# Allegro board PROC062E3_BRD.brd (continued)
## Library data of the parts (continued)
C58-C61 = CAP: signal model: CAP_CAP0402_0-75_0.01UF_0.01uF
D1 = DIODE
D2 = DIODE_TVS_DUAL
D3 D5 D6 D8 D9 D15 D17 = DIODE_SCHOTTKY
D4 D16 = DIODE_ZENER_SOT23_13
D7 D10-D13 = DIODE_PESD
D14 = DIODE_ZENER
F1 = FUSE
FL1 FL3-FL7 FL9-FL36 FL38 = EMIFILTER_IND
FL2 = EMI_FILTER
FL8 = EMIFILTER_ACM
FL37 R1-R84 R87-R100 R103-R110 R112 R113 R115-R117 R119 R120 R122-R151 R153 R155 R156 R158-R161 R163-R167 R171-R179 R182 R184-R202 R210 R212-R225 R227-R233 R235-R240 R242-R252 R254-R297 R299-R341 R343-R347 R350-R354 R356-R359 R362-R409 R411-R429 R431 R440-R442 R447 R449-R458 R460 R462 R464 R467-R479 R481-R484 R486 R490 R495-R499 R501 R503-R516 R518 R520-R522 R524 R526-R528 R534-R536 R538-R540 R542-R593 R596 R600-R622 R624-R673 R675-R698 R700-R704 R707-R723 R728-R732 R735-R743 R745 = RESISTOR
J1 = CON_PWRJACK3_RAPC722
J2 = CON_POWERJACK_PD-40S
J3 = CON_USB_MINI-AB_10
J4 = HEADER_3X2
J5 = CON_BTOB_30X2_171446
J6 = HEADER_5X2
J8 J9 J33 J37 J43-J45 = HEADER_3X1
J10 = HEADER_10X2
J11 J30 = HEADER_6X1
J12 = CON_RJ45-14_LPJG16314A4NL
J13 J34 = CON_10X2
J14 = CON_RJ45-28_LPJG17512AONL
J15 J24-J29 J31 = HEADER_2X1
J16 J32 J36 = CON_PMC_30X2_F
J17 = CON_SDCARD9_1939870-1
J18 J35 = CON_PMC_60X2_HQCD
J19 = HEADER_7X1
J20 J21 = HEADER_5X1
J22 = CON_PMC_20X2_F
J23 J42 = CON_MUSB-B_5_1051640001
J38 = CON_FLEX_40X1_SH4
J39 = CON_FLEX_36X1_52559-3652
J40 = CON_5X2
J41 = CON_FLEX_40X1_FH12A-40S-0.5SH
L1-L11 = INDUCTOR
LD1-LD6 LD8-LD17 = LED_598-8170-107F
LD7 LD19 LD20 = DIODE_LED
LD18 = LED3_SML-LX15IGC
Q1 Q2 = MOSFET_IRFZ24NS
Q3-Q6 Q9-Q17 = MOSFET_BSS138LT1G
Q7 = MOSFET_IRLML6401TR
Q8 = MOSFET_BSS138
R101 R102 R111 R114 R118 R121 R152 R154 R157 R162 R168 R180 R181 R183 R209 R211 R438 R439 R463 R466 R494 R500 R517 R519 R523 R525 R537 R541 = RESISTOR: signal model: RES
R169 R170 R203-R208 R241 R253 R410 R430 R432 R448 R489 R491 R532 R533 R623 R674 R699 = RESISTOR: signal model: RESISTOR_RES0402_22E_22E
R234 R342 R348 R349 R355 R360 R361 R459 = RESISTOR-4TERM
R594 R595 R597-R599 = RESISTOR: signal model: RESISTOR_RES0201_100E_100E
R705 R706 = RESISTOR: signal model: RESISTOR_RES0402_0-5_10E_10E
R724-R727 = RESISTOR: signal model: RESISTOR_RES0402_22E_1%_22E_1%
RA1 RA3 RA5 RA9-RA11 = RESARR_ISO8_0402: signal model: RESA
RA2 RA4 RA7 = RESARR_ISO4: signal model: RESA1
RA6 RA12 RA13 RA15-RA17 = RESARR_ISO4
RA8 RA14 = RESARR_ISO8: signal model: RESARR_ISO8_RESA_0402-8_22E_22E
SW1 = SW3_B12JV
SW2 SW3 = SW10_218-10LPST
SW4 = SW4_CHS-02TA
SW5-SW8 = SW4_SKHUPLE010
TP1-TP32 TP34-TP62 TP64-TP76 TP79-TP88 = TESTPOINT
U1 = TLV71318PDQNR_X2SON4
U2 U3 U27 U67-U70 U93 = INA226AIDGS_MSOP10
U4 = TPD4S012DRY_SON6
U5 U76 = TPS73501DRVR_SON6
U6 U12 U19 U21 U85 = SN74AVC4T245RSV_UQFN16
U7 U46 = TCA9554APWR_TSSOP16
U8 U23 U65 U83 = SN74LVC2G157DCUR_VSSOP8
U9 = 24LC512-ESN_SOIC8
U10 = TPS51206DSQR_WSON10
U11 U115 = TPS2051BD_SOIC8
U13 U18 = MOSFET_SI4442DY
U14 = LM25118MH_HTSSOP20
U15 U58 = TPD4E004_SON6
U16 U20 U25 U33 U38 = MT40A1G8WE-083_FBGA78
U17 U39 U41 U90 U92 = SN74LVC1G32DBVR_SOT23-5
U22 U31 U88 = DP83867IRRGZ_VQFN48
U24 = MT25QL02GCBB8E12_TPBGA24
U26 = TS3L110PWG4_TSSOP16
U28 U48 U53 U55 U74 U82 U86 U104 U108 U113 = SN74LVC1G08DBVRE4_SOT23-5
U29 U109 = SN74AVC2T245RSWR_QFN10
U30 U37 U45 U87 U96 U103 = TXS0102DCUR_VSSOP8
U32 = CDCLVC1310RHBR_VQFN32
U34 = AM654X_BGA784
U35 = TPS3711DDCR_SOT23-6
U36 = SN74LVC1G04DCKR_SC70-5
U40 U63 = TPS62097RWKT_VQFNHR11
U42 = SN74CB3Q3257PWR_TSSOP16
U43 U95 U98 = SN74AVC4T245RGYR_QFN16
U44 U89 = TMP100NA/3K_SOT23-6
U47 = TPD6E001RSE_UQFN10
U49 = TPS3897ADRYR_SON6
U50 = SN74LVC1G11DCKR_SC70-6
U51 = MTFC16GAKAEJP_VFBGA153
U52 U54 = SN74LVC3G17DCUR_VSSOP8
U56 = AT24HC04B-TH-B_TSSOP8
U57 = TPS79601DRBR_SON8
U59 = TPS6236X_DSBGA16
U60 = LP5912-1-8DRVT_WSON6
U61 = TPS62480RNCT_VQFNHR16
U62 = MIC5060YML_MLF8
U64 = TPS62095RGTR_VQFN16
U66 = LM5060_MSOP10
U71 U72 U78 U81 = MOSFET_CSD18501Q5A
U73 = FT4232H _LQFP64
U75 = LM5140QRWGTQ1_VQFNP40
U77 = MT35XU512ABA1G12_TPBGA24
U79 = 93LC46B_MSOP8
U80 = TPS54334DRCT_VSON10
U84 = TPIC2810D_SOIC16
U91 = MCP79410_SOIC8
U94 = TPS62085RLTR_VSONHR7
U97 U101 = SN74AVC2T244DQMR_X2SON8
U99 = TCA6424ARGJR_QFN32
U100 = TXB0108RGYR_VQFN20
U102 U105 = SN74AVC8T245RHL_QFN24
U106 = TM4C1294NCPDTT3R_TQFP128
U107 = LM4040B25IDCKR_SC70-5
U110 = TCA9555RTWR_WQFN24
U111 = TXS0108ERGYR_QFN20
U112 U114 = OSC_KC2520B
Y1-Y3 Y5 = CRY
Y4 Y6 = CRY4_13

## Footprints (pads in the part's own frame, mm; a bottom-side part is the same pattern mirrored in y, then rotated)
BATTH2_796136_1080X750_SMD_6-9
  rect 3.15x4.775 smd: 1(-15.52,0) 2(15.52,0)
BGA784_31-49_910X910_1-7
  round 0.457 smd: A1(-10.8,10.8) A2(-10,10.8) A3(-9.2,10.8) A4(-8.4,10.8) A5(-7.6,10.8) A6(-6.8,10.8) A7(-6,10.8) A8(-5.2,10.8) A9(-4.4,10.8) A10(-3.6,10.8) A11(-2.8,10.8) A12(-2,10.8) A13(-1.2,10.8) A14(-0.4,10.8) A15(0.4,10.8) A16(1.2,10.8) A17(2,10.8) A18(2.8,10.8) A19(3.6,10.8) A20(4.4,10.8) A21(5.2,10.8) A22(6,10.8) A23(6.8,10.8) A24(7.6,10.8) A25(8.4,10.8) A26(9.2,10.8) A27(10,10.8) A28(10.8,10.8) AA1(-10.8,-5.2) AA2(-10,-5.2) AA3(-9.2,-5.2) AA4(-8.4,-5.2) AA5(-7.6,-5.2) AA6(-6.8,-5.2) AA7(-6,-5.2) AA8(-5.2,-5.2) AA9(-4.4,-5.2) AA10(-3.6,-5.2) AA11(-2.8,-5.2) AA12(-2,-5.2) AA13(-1.2,-5.2) AA14(-0.4,-5.2) AA15(0.4,-5.2) AA16(1.2,-5.2) AA17(2,-5.2) AA18(2.8,-5.2) AA19(3.6,-5.2) AA20(4.4,-5.2) AA21(5.2,-5.2) AA22(6,-5.2) AA23(6.8,-5.2) AA24(7.6,-5.2) AA25(8.4,-5.2) AA26(9.2,-5.2) AA27(10,-5.2) AA28(10.8,-5.2) AB1(-10.8,-6) AB2(-10,-6) AB3(-9.2,-6) AB4(-8.4,-6) AB5(-7.6,-6) AB6(-6.8,-6) AB7(-6,-6) AB8(-5.2,-6) AB9(-4.4,-6) AB10(-3.6,-6) AB11(-2.8,-6) AB12(-2,-6) AB13(-1.2,-6) AB14(-0.4,-6) AB15(0.4,-6) AB16(1.2,-6) AB17(2,-6) AB18(2.8,-6) AB19(3.6,-6) AB20(4.4,-6) AB21(5.2,-6) AB22(6,-6) AB23(6.8,-6) AB24(7.6,-6) AB25(8.4,-6) AB26(9.2,-6) AB27(10,-6) AB28(10.8,-6) AC1(-10.8,-6.8) AC2(-10,-6.8) AC3(-9.2,-6.8) AC4(-8.4,-6.8) AC5(-7.6,-6.8) AC6(-6.8,-6.8) AC7(-6,-6.8) AC8(-5.2,-6.8) AC9(-4.4,-6.8) AC10(-3.6,-6.8) AC11(-2.8,-6.8) AC12(-2,-6.8) AC13(-1.2,-6.8) AC14(-0.4,-6.8) AC15(0.4,-6.8) AC16(1.2,-6.8) AC17(2,-6.8) AC18(2.8,-6.8) AC19(3.6,-6.8) AC20(4.4,-6.8) AC21(5.2,-6.8) AC22(6,-6.8) AC23(6.8,-6.8) AC24(7.6,-6.8) AC25(8.4,-6.8) AC26(9.2,-6.8) AC27(10,-6.8) AC28(10.8,-6.8) AD1(-10.8,-7.6) AD2(-10,-7.6) AD3(-9.2,-7.6) AD4(-8.4,-7.6) AD5(-7.6,-7.6) AD6(-6.8,-7.6) AD7(-6,-7.6) AD8(-5.2,-7.6) AD9(-4.4,-7.6) AD10(-3.6,-7.6) AD11(-2.8,-7.6) AD12(-2,-7.6) AD13(-1.2,-7.6) AD14(-0.4,-7.6) AD15(0.4,-7.6) AD16(1.2,-7.6) AD17(2,-7.6) AD18(2.8,-7.6) AD19(3.6,-7.6) AD20(4.4,-7.6) AD21(5.2,-7.6) AD22(6,-7.6) AD23(6.8,-7.6) AD24(7.6,-7.6) AD25(8.4,-7.6) AD26(9.2,-7.6) AD27(10,-7.6) AD28(10.8,-7.6) AE1(-10.8,-8.4) AE2(-10,-8.4) AE3(-9.2,-8.4) AE4(-8.4,-8.4) AE5(-7.6,-8.4) AE6(-6.8,-8.4) AE7(-6,-8.4) AE8(-5.2,-8.4) AE9(-4.4,-8.4) AE10(-3.6,-8.4) AE11(-2.8,-8.4) AE12(-2,-8.4) AE13(-1.2,-8.4) AE14(-0.4,-8.4) AE15(0.4,-8.4) AE16(1.2,-8.4) AE17(2,-8.4) AE18(2.8,-8.4) AE19(3.6,-8.4) AE20(4.4,-8.4) AE21(5.2,-8.4) AE22(6,-8.4) AE23(6.8,-8.4) AE24(7.6,-8.4) AE25(8.4,-8.4) AE26(9.2,-8.4) AE27(10,-8.4) AE28(10.8,-8.4) AF1(-10.8,-9.2) AF2(-10,-9.2) AF3(-9.2,-9.2) AF4(-8.4,-9.2) AF5(-7.6,-9.2) AF6(-6.8,-9.2) AF7(-6,-9.2) AF8(-5.2,-9.2) AF9(-4.4,-9.2) AF10(-3.6,-9.2) AF11(-2.8,-9.2) AF12(-2,-9.2) AF13(-1.2,-9.2) AF14(-0.4,-9.2) AF15(0.4,-9.2) AF16(1.2,-9.2) AF17(2,-9.2) AF18(2.8,-9.2) AF19(3.6,-9.2) AF20(4.4,-9.2) AF21(5.2,-9.2) AF22(6,-9.2) AF23(6.8,-9.2) AF24(7.6,-9.2) AF25(8.4,-9.2) AF26(9.2,-9.2) AF27(10,-9.2) AF28(10.8,-9.2) AG1(-10.8,-10) AG2(-10,-10) AG3(-9.2,-10) AG4(-8.4,-10) AG5(-7.6,-10) AG6(-6.8,-10) AG7(-6,-10) AG8(-5.2,-10) AG9(-4.4,-10) AG10(-3.6,-10) AG11(-2.8,-10) AG12(-2,-10) AG13(-1.2,-10) AG14(-0.4,-10) AG15(0.4,-10) AG16(1.2,-10) AG17(2,-10) AG18(2.8,-10) AG19(3.6,-10) AG20(4.4,-10) AG21(5.2,-10) AG22(6,-10) AG23(6.8,-10) AG24(7.6,-10) AG25(8.4,-10) AG26(9.2,-10) AG27(10,-10) AG28(10.8,-10) AH1(-10.8,-10.8) AH2(-10,-10.8) AH3(-9.2,-10.8) AH4(-8.4,-10.8) AH5(-7.6,-10.8) AH6(-6.8,-10.8) AH7(-6,-10.8) AH8(-5.2,-10.8) AH9(-4.4,-10.8) AH10(-3.6,-10.8) AH11(-2.8,-10.8) AH12(-2,-10.8) AH13(-1.2,-10.8) AH14(-0.4,-10.8) AH15(0.4,-10.8) AH16(1.2,-10.8) AH17(2,-10.8) AH18(2.8,-10.8) AH19(3.6,-10.8) AH20(4.4,-10.8) AH21(5.2,-10.8) AH22(6,-10.8) AH23(6.8,-10.8) AH24(7.6,-10.8) AH25(8.4,-10.8) AH26(9.2,-10.8) AH27(10,-10.8) AH28(10.8,-10.8) B1(-10.8,10) B2(-10,10) B3(-9.2,10) B4(-8.4,10) B5(-7.6,10) B6(-6.8,10) B7(-6,10) B8(-5.2,10) B9(-4.4,10) B10(-3.6,10) B11(-2.8,10) B12(-2,10) B13(-1.2,10) B14(-0.4,10) B15(0.4,10) B16(1.2,10) B17(2,10) B18(2.8,10) B19(3.6,10) B20(4.4,10) B21(5.2,10) B22(6,10) B23(6.8,10) B24(7.6,10) B25(8.4,10) B26(9.2,10) B27(10,10) B28(10.8,10) C1(-10.8,9.2) C2(-10,9.2) C3(-9.2,9.2) C4(-8.4,9.2) C5(-7.6,9.2) C6(-6.8,9.2) C7(-6,9.2) C8(-5.2,9.2) C9(-4.4,9.2) C10(-3.6,9.2) C11(-2.8,9.2) C12(-2,9.2) C13(-1.2,9.2) C14(-0.4,9.2) C15(0.4,9.2) C16(1.2,9.2) C17(2,9.2) C18(2.8,9.2) C19(3.6,9.2) C20(4.4,9.2) C21(5.2,9.2) C22(6,9.2) C23(6.8,9.2) C24(7.6,9.2) C25(8.4,9.2) C26(9.2,9.2) C27(10,9.2) C28(10.8,9.2) D1(-10.8,8.4) D2(-10,8.4) D3(-9.2,8.4) D4(-8.4,8.4) D5(-7.6,8.4) D6(-6.8,8.4) D7(-6,8.4) D8(-5.2,8.4) D9(-4.4,8.4) D10(-3.6,8.4) D11(-2.8,8.4) D12(-2,8.4) D13(-1.2,8.4) D14(-0.4,8.4) D15(0.4,8.4) D16(1.2,8.4) D17(2,8.4) D18(2.8,8.4) D19(3.6,8.4) D20(4.4,8.4) D21(5.2,8.4) D22(6,8.4) D23(6.8,8.4) D24(7.6,8.4) D25(8.4,8.4) D26(9.2,8.4) D27(10,8.4) D28(10.8,8.4) E1(-10.8,7.6) E2(-10,7.6) E3(-9.2,7.6) E4(-8.4,7.6) E5(-7.6,7.6) E6(-6.8,7.6) E7(-6,7.6) E8(-5.2,7.6) E9(-4.4,7.6) E10(-3.6,7.6) E11(-2.8,7.6) E12(-2,7.6) E13(-1.2,7.6) E14(-0.4,7.6) E15(0.4,7.6) E16(1.2,7.6) E17(2,7.6) E18(2.8,7.6) E19(3.6,7.6) E20(4.4,7.6) E21(5.2,7.6) E22(6,7.6) E23(6.8,7.6) E24(7.6,7.6) E25(8.4,7.6) E26(9.2,7.6) E27(10,7.6) E28(10.8,7.6) F1(-10.8,6.8) F2(-10,6.8) F3(-9.2,6.8) F4(-8.4,6.8) F5(-7.6,6.8) F6(-6.8,6.8) F7(-6,6.8) F8(-5.2,6.8) F9(-4.4,6.8) F10(-3.6,6.8) F11(-2.8,6.8) F12(-2,6.8) F13(-1.2,6.8) F14(-0.4,6.8) F15(0.4,6.8) F16(1.2,6.8) F17(2,6.8) F18(2.8,6.8) F19(3.6,6.8) F20(4.4,6.8) F21(5.2,6.8) F22(6,6.8) F23(6.8,6.8) F24(7.6,6.8) F25(8.4,6.8) F26(9.2,6.8) F27(10,6.8) F28(10.8,6.8) G1(-10.8,6) G2(-10,6) G3(-9.2,6) G4(-8.4,6) G5(-7.6,6) G6(-6.8,6) G7(-6,6) G8(-5.2,6) G9(-4.4,6) G10(-3.6,6) G11(-2.8,6) G12(-2,6) G13(-1.2,6) G14(-0.4,6) G15(0.4,6) G16(1.2,6) G17(2,6) G18(2.8,6) G19(3.6,6) G20(4.4,6) G21(5.2,6) G22(6,6) G23(6.8,6) G24(7.6,6) G25(8.4,6) G26(9.2,6) G27(10,6) G28(10.8,6) H1(-10.8,5.2) H2(-10,5.2) H3(-9.2,5.2) H4(-8.4,5.2) H5(-7.6,5.2) H6(-6.8,5.2) H7(-6,5.2) H8(-5.2,5.2) H9(-4.4,5.2) H10(-3.6,5.2) H11(-2.8,5.2) H12(-2,5.2) H13(-1.2,5.2) H14(-0.4,5.2) H15(0.4,5.2) H16(1.2,5.2) H17(2,5.2) H18(2.8,5.2) H19(3.6,5.2) H20(4.4,5.2) H21(5.2,5.2) H22(6,5.2) H23(6.8,5.2) H24(7.6,5.2) H25(8.4,5.2) H26(9.2,5.2) H27(10,5.2) H28(10.8,5.2) J1(-10.8,4.4) J2(-10,4.4) J3(-9.2,4.4) J4(-8.4,4.4) J5(-7.6,4.4) J6(-6.8,4.4) J7(-6,4.4) J8(-5.2,4.4) J9(-4.4,4.4) J10(-3.6,4.4) J11(-2.8,4.4) J12(-2,4.4) J13(-1.2,4.4) J14(-0.4,4.4) J15(0.4,4.4) J16(1.2,4.4) J17(2,4.4) J18(2.8,4.4) J19(3.6,4.4) J20(4.4,4.4) J21(5.2,4.4) J22(6,4.4) J23(6.8,4.4) J24(7.6,4.4) J25(8.4,4.4) J26(9.2,4.4) J27(10,4.4) J28(10.8,4.4) K1(-10.8,3.6) K2(-10,3.6) K3(-9.2,3.6) K4(-8.4,3.6) K5(-7.6,3.6) K6(-6.8,3.6) K7(-6,3.6) K8(-5.2,3.6) K9(-4.4,3.6) K10(-3.6,3.6) K11(-2.8,3.6) K12(-2,3.6) K13(-1.2,3.6) K14(-0.4,3.6) K15(0.4,3.6) K16(1.2,3.6) K17(2,3.6) K18(2.8,3.6) K19(3.6,3.6) K20(4.4,3.6) K21(5.2,3.6) K22(6,3.6) K23(6.8,3.6) K24(7.6,3.6) K25(8.4,3.6) K26(9.2,3.6) K27(10,3.6) K28(10.8,3.6) L1(-10.8,2.8) L2(-10,2.8) L3(-9.2,2.8) L4(-8.4,2.8) L5(-7.6,2.8) L6(-6.8,2.8) L7(-6,2.8) L8(-5.2,2.8) L9(-4.4,2.8) L10(-3.6,2.8) L11(-2.8,2.8) L12(-2,2.8) L13(-1.2,2.8) L14(-0.4,2.8) L15(0.4,2.8) L16(1.2,2.8) L17(2,2.8) L18(2.8,2.8) L19(3.6,2.8) L20(4.4,2.8) L21(5.2,2.8) L22(6,2.8) L23(6.8,2.8) L24(7.6,2.8) L25(8.4,2.8) L26(9.2,2.8) L27(10,2.8) L28(10.8,2.8) M1(-10.8,2) M2(-10,2) M3(-9.2,2) M4(-8.4,2) M5(-7.6,2) M6(-6.8,2) M7(-6,2) M8(-5.2,2) M9(-4.4,2) M10(-3.6,2) M11(-2.8,2) M12(-2,2) M13(-1.2,2) M14(-0.4,2) M15(0.4,2) M16(1.2,2) M17(2,2) M18(2.8,2) M19(3.6,2) M20(4.4,2) M21(5.2,2) M22(6,2) M23(6.8,2) M24(7.6,2) M25(8.4,2) M26(9.2,2) M27(10,2) M28(10.8,2) N1(-10.8,1.2) N2(-10,1.2) N3(-9.2,1.2) N4(-8.4,1.2) N5(-7.6,1.2) N6(-6.8,1.2) N7(-6,1.2) N8(-5.2,1.2) N9(-4.4,1.2) N10(-3.6,1.2) N11(-2.8,1.2) N12(-2,1.2) N13(-1.2,1.2) N14(-0.4,1.2) N15(0.4,1.2) N16(1.2,1.2) N17(2,1.2) N18(2.8,1.2) N19(3.6,1.2) N20(4.4,1.2) N21(5.2,1.2) N22(6,1.2) N23(6.8,1.2) N24(7.6,1.2) N25(8.4,1.2) N26(9.2,1.2) N27(10,1.2) N28(10.8,1.2) P1(-10.8,0.4) P2(-10,0.4) P3(-9.2,0.4) P4(-8.4,0.4) P5(-7.6,0.4) P6(-6.8,0.4) P7(-6,0.4) P8(-5.2,0.4) P9(-4.4,0.4) P10(-3.6,0.4) P11(-2.8,0.4) P12(-2,0.4) P13(-1.2,0.4) P14(-0.4,0.4) P15(0.4,0.4) P16(1.2,0.4) P17(2,0.4) P18(2.8,0.4) P19(3.6,0.4) P20(4.4,0.4) P21(5.2,0.4) P22(6,0.4) P23(6.8,0.4) P24(7.6,0.4) P25(8.4,0.4) P26(9.2,0.4) P27(10,0.4) P28(10.8,0.4) R1(-10.8,-0.4) R2(-10,-0.4) R3(-9.2,-0.4) R4(-8.4,-0.4) R5(-7.6,-0.4) R6(-6.8,-0.4) R7(-6,-0.4) R8(-5.2,-0.4) R9(-4.4,-0.4) R10(-3.6,-0.4) R11(-2.8,-0.4) R12(-2,-0.4) R13(-1.2,-0.4) R14(-0.4,-0.4) R15(0.4,-0.4) R16(1.2,-0.4) R17(2,-0.4) R18(2.8,-0.4) R19(3.6,-0.4) R20(4.4,-0.4) R21(5.2,-0.4) R22(6,-0.4) R23(6.8,-0.4) R24(7.6,-0.4) R25(8.4,-0.4) R26(9.2,-0.4) R27(10,-0.4) R28(10.8,-0.4) T1(-10.8,-1.2) T2(-10,-1.2) T3(-9.2,-1.2) T4(-8.4,-1.2) T5(-7.6,-1.2) T6(-6.8,-1.2) T7(-6,-1.2) T8(-5.2,-1.2) T9(-4.4,-1.2) T10(-3.6,-1.2) T11(-2.8,-1.2) T12(-2,-1.2) T13(-1.2,-1.2) T14(-0.4,-1.2) T15(0.4,-1.2) T16(1.2,-1.2) T17(2,-1.2) T18(2.8,-1.2) T19(3.6,-1.2) T20(4.4,-1.2) T21(5.2,-1.2) T22(6,-1.2) T23(6.8,-1.2) T24(7.6,-1.2) T25(8.4,-1.2) T26(9.2,-1.2) T27(10,-1.2) T28(10.8,-1.2) U1(-10.8,-2) U2(-10,-2) U3(-9.2,-2) U4(-8.4,-2) U5(-7.6,-2) U6(-6.8,-2) U7(-6,-2) U8(-5.2,-2) U9(-4.4,-2) U10(-3.6,-2) U11(-2.8,-2) U12(-2,-2) U13(-1.2,-2) U14(-0.4,-2) U15(0.4,-2) U16(1.2,-2) U17(2,-2) U18(2.8,-2) U19(3.6,-2) U20(4.4,-2) U21(5.2,-2) U22(6,-2) U23(6.8,-2) U24(7.6,-2) U25(8.4,-2) U26(9.2,-2) U27(10,-2) U28(10.8,-2) V1(-10.8,-2.8) V2(-10,-2.8) V3(-9.2,-2.8) V4(-8.4,-2.8) V5(-7.6,-2.8) V6(-6.8,-2.8) V7(-6,-2.8) V8(-5.2,-2.8) V9(-4.4,-2.8) V10(-3.6,-2.8) V11(-2.8,-2.8) V12(-2,-2.8) V13(-1.2,-2.8) V14(-0.4,-2.8) V15(0.4,-2.8) V16(1.2,-2.8) V17(2,-2.8) V18(2.8,-2.8) V19(3.6,-2.8) V20(4.4,-2.8) V21(5.2,-2.8) V22(6,-2.8) V23(6.8,-2.8) V24(7.6,-2.8) V25(8.4,-2.8) V26(9.2,-2.8) V27(10,-2.8) V28(10.8,-2.8) W1(-10.8,-3.6) W2(-10,-3.6) W3(-9.2,-3.6) W4(-8.4,-3.6) W5(-7.6,-3.6) W6(-6.8,-3.6) W7(-6,-3.6) W8(-5.2,-3.6) W9(-4.4,-3.6) W10(-3.6,-3.6) W11(-2.8,-3.6) W12(-2,-3.6) W13(-1.2,-3.6) W14(-0.4,-3.6) W15(0.4,-3.6) W16(1.2,-3.6) W17(2,-3.6) W18(2.8,-3.6) W19(3.6,-3.6) W20(4.4,-3.6) W21(5.2,-3.6) W22(6,-3.6) W23(6.8,-3.6) W24(7.6,-3.6) W25(8.4,-3.6) W26(9.2,-3.6) W27(10,-3.6) W28(10.8,-3.6) Y1(-10.8,-4.4) Y2(-10,-4.4) Y3(-9.2,-4.4) Y4(-8.4,-4.4) Y5(-7.6,-4.4) Y6(-6.8,-4.4) Y7(-6,-4.4) Y8(-5.2,-4.4) Y9(-4.4,-4.4) Y10(-3.6,-4.4) Y11(-2.8,-4.4) Y12(-2,-4.4) Y13(-1.2,-4.4) Y14(-0.4,-4.4) Y15(0.4,-4.4) Y16(1.2,-4.4) Y17(2,-4.4) Y18(2.8,-4.4) Y19(3.6,-4.4) Y20(4.4,-4.4) Y21(5.2,-4.4) Y22(6,-4.4) Y23(6.8,-4.4) Y24(7.6,-4.4) Y25(8.4,-4.4) Y26(9.2,-4.4) Y27(10,-4.4) Y28(10.8,-4.4)
CAP0201_0-5
  rect 0.356x0.33 smd: 1(-0.28,0) 2(0.28,0)
CAP0402
  rect 0.483x0.584 smd: 1(-0.46,0) 2(0.46,0)
CAP0402_0-75
  rect 0.483x0.584 smd: 1(-0.46,0) 2(0.46,0)
CAP0603
  rect 0.711x0.889 smd: 1(-0.7,0) 2(0.7,0)
CAP0603_1
  rect 0.711x0.889 smd: 1(-0.7,0) 2(0.7,0)
CAP0805_1
  rect 0.94x1.346 smd: 1(-0.8,0) 2(0.8,0)
CAP0805_1-5
  rect 0.94x1.346 smd: 1(-0.8,0) 2(0.8,0)
CAP1206
  rect 0.991x1.702 smd: 1(-1.35,0) 2(1.35,0)
CAP1206_2
  rect 0.991x1.702 smd: 1(-1.35,0) 2(1.35,0)
CAP7563_4
  rect 1.143x6.807 smd: 1(-3.8,0) 2(3.8,0)
CAP_87510524_270X270_SMD_7-7
  rect 3.505x1.6 smd: 1(-2.8,0) 2(2.8,0)
CAPAE_CASE8383_11
  rect 3.861x2.159 smd: 1(-3.45,0) 2(3.45,0)
CAPAE_CASE103103_11
  rect 4.14x2.159 smd: 1(-4.3,0) 2(4.3,0)
CAPAE_D8CASE_8
  rect 3.15x1.6 smd: 1(-2.9,0) 2(2.9,0)
CAPAE_GCASE
  rect 4.293x2.108 smd: 1(-4.45,0) 2(4.45,0)
CAPT7343D_3-25
  rect 2.362x2.438 smd: 1(-3.1,0) 2(3.1,0)
CON_2X5_TC2050-IDC-430-NL_T
  round 0.94 hole 1.067 unplated: (-3.81,0) (3.81,-1.015) (3.81,1.015)
  round 0.864 smd: 1(-2.54,-0.635) 2(-1.27,-0.635) 3(0,-0.635) 4(1.27,-0.635) 5(2.54,-0.635) 6(2.54,0.635) 7(1.27,0.635) 8(0,0.635) 9(-1.27,0.635) 10(-2.54,0.635)
CON_10X2_FTR-110-51-S-D_P_S_S
  rect 0.711x2.87 smd: 1(-5.715,-2.705) 2(-5.715,2.705) 3(-4.445,-2.705) 4(-4.445,2.705) 5(-3.175,-2.705) 6(-3.175,2.705) 7(-1.905,-2.705) 8(-1.905,2.705) 9(-0.635,-2.705) 10(-0.635,2.705) 11(0.635,-2.705) 12(0.635,2.705) 13(1.905,-2.705) 14(1.905,2.705) 15(3.175,-2.705) 16(3.175,2.705) 17(4.445,-2.705) 18(4.445,2.705) 19(5.715,-2.705) 20(5.715,2.705)
CON_BTOB2X30_171446_P_S_S_5-5
  round 0.737 hole 0.864 unplated: (-13.05,1.25) (13.05,-1.25)
  rect 0.508x1.702 smd: 1(-11.6,-1.115) 2(-10.8,-1.115) 3(-10,-1.115) 4(-9.2,-1.115) 5(-8.4,-1.115) 6(-7.6,-1.115) 7(-6.8,-1.115) 8(-6,-1.115) 9(-5.2,-1.115) 10(-4.4,-1.115) 11(-3.6,-1.115) 12(-2.8,-1.115) 13(-2,-1.115) 14(-1.2,-1.115) 15(-0.4,-1.115) 16(0.4,-1.115) 17(1.2,-1.115) 18(2,-1.115) 19(2.8,-1.115) 20(3.6,-1.115) 21(4.4,-1.115) 22(5.2,-1.115) 23(6,-1.115) 24(6.8,-1.115) 25(7.6,-1.115) 26(8.4,-1.115) 27(9.2,-1.115) 28(10,-1.115) 29(10.8,-1.115) 30(11.6,-1.115) 31(-11.6,1.115) 32(-10.8,1.115) 33(-10,1.115) 34(-9.2,1.115) 35(-8.4,1.115) 36(-7.6,1.115) 37(-6.8,1.115) 38(-6,1.115) 39(-5.2,1.115) 40(-4.4,1.115) 41(-3.6,1.115) 42(-2.8,1.115) 43(-2,1.115) 44(-1.2,1.115) 45(-0.4,1.115) 46(0.4,1.115) 47(1.2,1.115) 48(2,1.115) 49(2.8,1.115) 50(3.6,1.115) 51(4.4,1.115) 52(5.2,1.115) 53(6,1.115) 54(6.8,1.115) 55(7.6,1.115) 56(8.4,1.115) 57(9.2,1.115) 58(10,1.115) 59(10.8,1.115) 60(11.6,1.115)
  round 1.143 hole 0.813: SH1(-12.95,0) SH2(12.95,0)
CON_FLEX1X36_52559-36_S_S_S_5-3
  rect 0.61x1.499 smd: 1(-8.75,-1.4) 2(-8.25,1.4) 3(-7.75,-1.4) 4(-7.25,1.4) 5(-6.75,-1.4) 6(-6.25,1.4) 7(-5.75,-1.4) 8(-5.25,1.4) 9(-4.75,-1.4) 10(-4.25,1.4) 11(-3.75,-1.4) 12(-3.25,1.4) 13(-2.75,-1.4) 14(-2.25,1.4) 15(-1.75,-1.4) 16(-1.25,1.4) 17(-0.75,-1.4) 18(-0.25,1.4) 19(0.25,-1.4) 20(0.75,1.4) 21(1.25,-1.4) 22(1.75,1.4) 23(2.25,-1.4) 24(2.75,1.4) 25(3.25,-1.4) 26(3.75,1.4) 27(4.25,-1.4) 28(4.75,1.4) 29(5.25,-1.4) 30(5.75,1.4) 31(6.25,-1.4) 32(6.75,1.4) 33(7.25,-1.4) 34(7.75,1.4) 35(8.25,-1.4) 36(8.75,1.4)
  rect 0.787x1.499 smd: SH1(-9.75,-1.4) SH2(-9.75,1.4) SH3(9.75,-1.4) SH4(9.75,1.4)
CON_FLEX1X40_20720-040_S_R_S_2
  rect 0.279x0.991 smd: 1(-9.75,2.556) 2(-9.25,2.556) 3(-8.75,2.556) 4(-8.25,2.556) 5(-7.75,2.556) 6(-7.25,2.556) 7(-6.75,2.556) 8(-6.25,2.556) 9(-5.75,2.556) 10(-5.25,2.556) 11(-4.75,2.556) 12(-4.25,2.556) 13(-3.75,2.556) 14(-3.25,2.556) 15(-2.75,2.556) 16(-2.25,2.556) 17(-1.75,2.556) 18(-1.25,2.556) 19(-0.75,2.556) 20(-0.25,2.556) 21(0.25,2.556) 22(0.75,2.556) 23(1.25,2.556) 24(1.75,2.556) 25(2.25,2.556) 26(2.75,2.556) 27(3.25,2.556) 28(3.75,2.556) 29(4.25,2.556) 30(4.75,2.556) 31(5.25,2.556) 32(5.75,2.556) 33(6.25,2.556) 34(6.75,2.556) 35(7.25,2.556) 36(7.75,2.556) 37(8.25,2.556) 38(8.75,2.556) 39(9.25,2.556) 40(9.75,2.556)
  rect 0.61x0.991 smd: SH1(-10.65,2.556) SH2(10.65,2.556)
  rect 1.499x2.007 smd: SH3(-12.85,-0.264) SH4(12.85,-0.264)
CON_FLEX40X1_FH12A_S_R_S
  rect 0.33x1.397 smd: 1(-9.75,3.575) 2(-9.25,3.575) 3(-8.75,3.575) 4(-8.25,3.575) 5(-7.75,3.575) 6(-7.25,3.575) 7(-6.75,3.575) 8(-6.25,3.575) 9(-5.75,3.575) 10(-5.25,3.575) 11(-4.75,3.575) 12(-4.25,3.575) 13(-3.75,3.575) 14(-3.25,3.575) 15(-2.75,3.575) 16(-2.25,3.575) 17(-1.75,3.575) 18(-1.25,3.575) 19(-0.75,3.575) 20(-0.25,3.575) 21(0.25,3.575) 22(0.75,3.575) 23(1.25,3.575) 24(1.75,3.575) 25(2.25,3.575) 26(2.75,3.575) 27(3.25,3.575) 28(3.75,3.575) 29(4.25,3.575) 30(4.75,3.575) 31(5.25,3.575) 32(5.75,3.575) 33(6.25,3.575) 34(6.75,3.575) 35(7.25,3.575) 36(7.75,3.575) 37(8.25,3.575) 38(8.75,3.575) 39(9.25,3.575) 40(9.75,3.575)
  rect 1.803x2.311 smd: 41(-11.65,0.325) 42(11.65,0.325)
CON_MUSBB5_1051640001_S_R_S_2-5
  rect 0.457x1.372 smd: 1(1.3,2.143) 2(0.65,2.143) 3(0,2.143) 4(-0.65,2.143) 5(-1.3,2.143)
  oval 1.397x2.108 hole 0.61x1.321: SH1(-3.95,-0.517) SH2(3.95,-0.517)
  rect 1.473x2.108 smd: SH3(-2.462,1.783) SH4(2.462,1.783)
  rect 1.372x1.905 smd: SH5(-0.937,-0.517) SH6(0.937,-0.517)
CON_PMC20X2_QSH-D-DP_S_S_S
  round 0.889 hole 1.016 unplated: (-9.56,2.67) (10.573,2.67)
  rect 0.279x2.286 smd: 1(-6.75,-2.87) 2(-6.75,2.87) 3(-6.25,-2.87) 4(-6.25,2.87) 5(-5.25,-2.87) 6(-5.25,2.87) 7(-4.75,-2.87) 8(-4.75,2.87) 9(-3.75,-2.87) 10(-3.75,2.87) 11(-3.25,-2.87) 12(-3.25,2.87) 13(-2.25,-2.87) 14(-2.25,2.87) 15(-1.75,-2.87) 16(-1.75,2.87) 17(-0.75,-2.87) 18(-0.75,2.87) 19(-0.25,-2.87) 20(-0.25,2.87) 21(0.75,-2.87) 22(0.75,2.87) 23(1.25,-2.87) 24(1.25,2.87) 25(2.25,-2.87) 26(2.25,2.87) 27(2.75,-2.87) 28(2.75,2.87) 29(3.75,-2.87) 30(3.75,2.87) 31(4.25,-2.87) 32(4.25,2.87) 33(5.25,-2.87) 34(5.25,2.87) 35(5.75,-2.87) 36(5.75,2.87) 37(6.75,-2.87) 38(6.75,2.87) 39(7.25,-2.87) 40(7.25,2.87)
  rect 2.54x0.432 smd: 41(-8.065,0) 44(8.065,0)
  rect 4.699x0.432 smd: 42(3.175,0) 43(-3.175,0)
CON_PMC30X2_QSH-030-01-L_S_S_S
  round 0.889 hole 1.016 unplated: (-10.06,2.67) (10.07,2.67)
  rect 0.279x2.286 smd: 1(-7.25,-2.87) 2(-7.25,2.87) 3(-6.75,-2.87) 4(-6.75,2.87) 5(-6.25,-2.87) 6(-6.25,2.87) 7(-5.75,-2.87) 8(-5.75,2.87) 9(-5.25,-2.87) 10(-5.25,2.87) 11(-4.75,-2.87) 12(-4.75,2.87) 13(-4.25,-2.87) 14(-4.25,2.87) 15(-3.75,-2.87) 16(-3.75,2.87) 17(-3.25,-2.87) 18(-3.25,2.87) 19(-2.75,-2.87) 20(-2.75,2.87) 21(-2.25,-2.87) 22(-2.25,2.87) 23(-1.75,-2.87) 24(-1.75,2.87) 25(-1.25,-2.87) 26(-1.25,2.87) 27(-0.75,-2.87) 28(-0.75,2.87) 29(-0.25,-2.87) 30(-0.25,2.87) 31(0.25,-2.87) 32(0.25,2.87) 33(0.75,-2.87) 34(0.75,2.87) 35(1.25,-2.87) 36(1.25,2.87) 37(1.75,-2.87) 38(1.75,2.87) 39(2.25,-2.87) 40(2.25,2.87) 41(2.75,-2.87) 42(2.75,2.87) 43(3.25,-2.87) 44(3.25,2.87) 45(3.75,-2.87) 46(3.75,2.87) 47(4.25,-2.87) 48(4.25,2.87) 49(4.75,-2.87) 50(4.75,2.87) 51(5.25,-2.87) 52(5.25,2.87) 53(5.75,-2.87) 54(5.75,2.87) 55(6.25,-2.87) 56(6.25,2.87) 57(6.75,-2.87) 58(6.75,2.87) 59(7.25,-2.87) 60(7.25,2.87)
  rect 2.54x0.432 smd: 61(8.065,0) 62(-8.065,0)
  rect 4.724x0.432 smd: 63(3.175,0) 64(-3.175,0)
CON_PMC60X2_HQCD-060_S_S_S_3-3
  round 0.889 hole 1.016 unplated: (-20.06,2.67) (20.07,2.67)
  rect 0.279x2.286 smd: 1(-17.25,-2.87) 2(-17.25,2.87) 3(-16.75,-2.87) 4(-16.75,2.87) 5(-16.25,-2.87) 6(-16.25,2.87) 7(-15.75,-2.87) 8(-15.75,2.87) 9(-15.25,-2.87) 10(-15.25,2.87) 11(-14.75,-2.87) 12(-14.75,2.87) 13(-14.25,-2.87) 14(-14.25,2.87) 15(-13.75,-2.87) 16(-13.75,2.87) 17(-13.25,-2.87) 18(-13.25,2.87) 19(-12.75,-2.87) 20(-12.75,2.87) 21(-12.25,-2.87) 22(-12.25,2.87) 23(-11.75,-2.87) 24(-11.75,2.87) 25(-11.25,-2.87) 26(-11.25,2.87) 27(-10.75,-2.87) 28(-10.75,2.87) 29(-10.25,-2.87) 30(-10.25,2.87) 31(-9.75,-2.87) 32(-9.75,2.87) 33(-9.25,-2.87) 34(-9.25,2.87) 35(-8.75,-2.87) 36(-8.75,2.87) 37(-8.25,-2.87) 38(-8.25,2.87) 39(-7.75,-2.87) 40(-7.75,2.87) 41(-7.25,-2.87) 42(-7.25,2.87) 43(-6.75,-2.87) 44(-6.75,2.87) 45(-6.25,-2.87) 46(-6.25,2.87) 47(-5.75,-2.87) 48(-5.75,2.87) 49(-5.25,-2.87) 50(-5.25,2.87) 51(-4.75,-2.87) 52(-4.75,2.87) 53(-4.25,-2.87) 54(-4.25,2.87) 55(-3.75,-2.87) 56(-3.75,2.87) 57(-3.25,-2.87) 58(-3.25,2.87) 59(-2.75,-2.87) 60(-2.75,2.87) 61(2.75,-2.87) 62(2.75,2.87) 63(3.25,-2.87) 64(3.25,2.87) 65(3.75,-2.87) 66(3.75,2.87) 67(4.25,-2.87) 68(4.25,2.87) 69(4.75,-2.87) 70(4.75,2.87) 71(5.25,-2.87) 72(5.25,2.87) 73(5.75,-2.87) 74(5.75,2.87) 75(6.25,-2.87) 76(6.25,2.87) 77(6.75,-2.87) 78(6.75,2.87) 79(7.25,-2.87) 80(7.25,2.87) 81(7.75,-2.87) 82(7.75,2.87) 83(8.25,-2.87) 84(8.25,2.87) 85(8.75,-2.87) 86(8.75,2.87) 87(9.25,-2.87) 88(9.25,2.87) 89(9.75,-2.87) 90(9.75,2.87) 91(10.25,-2.87) 92(10.25,2.87) 93(10.75,-2.87) 94(10.75,2.87) 95(11.25,-2.87) 96(11.25,2.87) 97(11.75,-2.87) 98(11.75,2.87) 99(12.25,-2.87) 100(12.25,2.87) 101(12.75,-2.87) 102(12.75,2.87) 103(13.25,-2.87) 104(13.25,2.87) 105(13.75,-2.87) 106(13.75,2.87) 107(14.25,-2.87) 108(14.25,2.87) 109(14.75,-2.87) 110(14.75,2.87) 111(15.25,-2.87) 112(15.25,2.87) 113(15.75,-2.87) 114(15.75,2.87) 115(16.25,-2.87) 116(16.25,2.87) 117(16.75,-2.87) 118(16.75,2.87) 119(17.25,-2.87) 120(17.25,2.87)
  rect 2.54x0.432 smd: 121(-18.06,0) 124(-1.93,0) 125(1.94,0) 128(18.07,0)
  rect 4.724x0.432 smd: 122(-13.17,0) 123(-6.82,0) 126(6.83,0) 127(13.18,0)
CON_POWERJACK4_PD-40S_S_R_T_15
  oval 1.295x3.2 hole 0.61x2.489: 1(0,0) 2(-5.8,0) 3(-0.4,3.65) 4(-5.4,3.65)
  oval 2.896x1.295 hole 2.184x0.61: 5(-2.9,9.15)
  oval 1.295x2.896 hole 0.61x2.184: 6(-10.7,-1.35) 7(4.9,-1.35)
  round 2.896 hole 2.184: SH1(-10.7,7.15) SH4(4.9,7.15)
  round 2.362 hole 1.676: SH2(-5.4,7.15) SH3(-0.4,7.15)
CON_PWRJACK3_RAPC722_P_R_T
  rect 4.826x2.032 hole 3.556x1.016: 1(0,0.024)
  rect 4.064x1.778 hole 3.048x0.762: 2(0,-6.226)
  rect 1.778x4.064 hole 0.762x3.048: 3(4.8,-2.976)
CON_RJ45-14_LPJG16314A4NL_S_R_T_13-6
  round 3.073 hole 3.2 unplated: (0,-8.89) (11.43,-8.89)
  rect 1.6x1.6 hole 0.914: 1(0,0)
  round 1.6 hole 0.914: 2(1.27,-2.54) 3(2.54,0) 4(3.81,-2.54) 5(5.08,0) 6(6.35,-2.54) 7(7.62,0) 8(8.89,-2.54) 9(10.16,0) 10(11.43,-2.54)
  round 1.702 hole 1.016: 11(12.44,-11.43) 12(12.44,-13.462) 13(-1.01,-11.43) 14(-1.01,-13.462)
  round 2.362 hole 1.676: 15(-2.032,-5.842) 16(13.462,-5.842)
CON_RJ45-28_LPJG17512_S_R_T_25-3
  round 3.073 hole 3.2 unplated: (-2.42,-4.71) (9.01,-4.71)
  round 1.6 hole 0.914: A1(0,0) A2(1.27,1.27) A3(0,2.54) A4(1.27,3.81) A5(0,5.08) A6(1.27,6.35) A7(0,7.62) A8(1.27,8.89) A9(0,10.16) A10(1.27,11.43) A11(6.34,-3.7) A12(4.31,-3.7) A13(2.28,-3.7) A14(0.25,-3.7) B1(6.6,0) B2(5.33,1.27) B3(6.6,2.54) B4(5.33,3.81) B5(6.6,5.08) B6(5.33,6.35) B7(6.6,7.62) B8(5.33,8.89) B9(6.6,10.16) B10(5.33,11.43) B11(6.34,-1.85) B12(4.31,-1.85) B13(2.28,-1.85) B14(0.25,-1.85)
  round 2.362 hole 1.676: SH1(-5.21,10.78) SH2(11.8,6.72) SH3(-5.21,-9.28) SH4(11.8,-9.28)
CON_SD9_1939870-1_S_R_S_2-9
  round 1.295 hole 1.422 unplated: (-11.97,-8.409) (11.97,-8.409)
  rect 0.94x2.159 smd: 1(6.255,14.191) 2(3.755,14.191) 3(1.255,14.191) 4(-1.245,14.191) 5(-3.745,14.191) 6(-6.245,14.191) 7(-8.67,14.191) 8(-10.37,14.191) 9(8.755,14.191)
  rect 0.838x1.245 smd: G1(-11.97,14.141)
  rect 1.168x0.94 smd: G2(-13.285,6.471)
  rect 1.168x1.549 smd: G3(-13.285,-6.839)
  rect 4.369x3.251 smd: G4(-11.69,-11.459) G5(12.09,-11.459)
CON_USBAB5_475900001_S_R_S_3-1
  rect 0.457x1.372 smd: 1(1.3,2.04) 2(0.65,2.04) 3(0,2.04) 4(-0.65,2.04) 5(-1.3,2.04)
  oval 1.067x1.499 hole 0.813: 6(2.225,2.365) 7(-2.225,2.365)
  custom 0.35x0.35 hole 0.813x1.626: 8(-4,-0.635) 9(4,-0.635)
  rect 2.896x2.007 smd: 10(0,-0.635)
D2PAK-3
  rect 1.27x3.429 smd: 1(-2.54,-6.229) 3(2.54,-6.229)
  rect 10.668x9.017 smd: 4(0,3.677)
DFN8_25-59_120X120_1
  rect 0.889x0.356 smd: 1(-1.45,0.975) 2(-1.45,0.325) 3(-1.45,-0.325) 4(-1.45,-0.975) 5(1.45,-0.975) 6(1.45,-0.325) 7(1.45,0.325) 8(1.45,0.975)
  rect 1.6x2.388 smd: 9(0,0)
DFN10_15-74_80X80_0-8
  rect 0.711x0.203 smd: 1(-1.05,0.8) 2(-1.05,0.4) 3(-1.05,0) 4(-1.05,-0.4) 5(-1.05,-0.8) 6(1.05,-0.8) 7(1.05,-0.4) 8(1.05,0) 9(1.05,0.4) 10(1.05,0.8)
  rect 0.94x1.6 smd: 11(0,0)
DIO_DFN0402
  rect 0.508x0.66 smd: 1(-0.42,0) 2(0.42,0)
DIO_SMA
  rect 1.88x1.651 smd: 1(-2.06,0) 2(2.06,0)
DIO_SMB_2-5
  rect 2.261x2.159 smd: 1(-2.2,0) 2(2.2,0)
DIO_SMC
  rect 2.21x3.099 smd: 1(-3.5,0) 2(3.5,0)
DIO_SOD323
  rect 0.762x0.457 smd: 1(-1.2,0) 2(1.2,0)
DIO_SOD323_1
  rect 1.092x0.508 smd: 1(-1.4,0) 2(1.4,0)
DO-214AB_5-6
  rect 2.21x5.207 smd: 1(-3.5,0) 2(3.5,0)
DSBGA16_19-68_80X80_0-7
  round 0.279 smd: A1(-0.75,0.75) A2(-0.25,0.75) A3(0.25,0.75) A4(0.75,0.75) B1(-0.75,0.25) B2(-0.25,0.25) B3(0.25,0.25) B4(0.75,0.25) C1(-0.75,-0.25) C2(-0.25,-0.25) C3(0.25,-0.25) C4(0.75,-0.25) D1(-0.75,-0.75) D2(-0.25,-0.75) D3(0.25,-0.75) D4(0.75,-0.75)
EMIFIL_BLM03B_0201
  rect 0.356x0.33 smd: 1(-0.28,0) 2(0.28,0)
EMIFIL_BLM15A_0402
  rect 0.61x0.61 smd: 1(-0.46,0) 2(0.46,0)
EMIFIL_BLM15A_0402_0-6
  rect 0.508x0.508 smd: 1(-0.41,0) 2(0.41,0)
EMIFIL_BLM18K_0603
  rect 0.94x1.194 smd: 1(-0.825,0) 2(0.825,0)
EMIFIL_BLM18R_0603_1
  rect 1.016x1.016 smd: 1(-0.85,0) 2(0.85,0)
EMIFIL_NFM21P_0805_1
  rect 0.61x0.61 smd: 1(-1,0) 3(1,0)
  rect 0.61x1.905 smd: 2(0,0)
ETSSOP20_25-59_260X180_1-1
  rect 1.499x0.457 smd: 1(-2.9,2.925) 2(-2.9,2.275) 3(-2.9,1.625) 4(-2.9,0.975) 5(-2.9,0.325) 6(-2.9,-0.325) 7(-2.9,-0.975) 8(-2.9,-1.625) 9(-2.9,-2.275) 10(-2.9,-2.925) 11(2.9,-2.925) 12(2.9,-2.275) 13(2.9,-1.625) 14(2.9,-0.975) 15(2.9,-0.325) 16(2.9,0.325) 17(2.9,0.975) 18(2.9,1.625) 19(2.9,2.275) 20(2.9,2.925)
  rect 3.15x4.343 smd: 21(0,0)
FBGA78_31-49_320X480_1-2
  round 0.457 smd: A1(-3.2,4.8) A2(-2.4,4.8) A3(-1.6,4.8) A7(1.6,4.8) A8(2.4,4.8) A9(3.2,4.8) B1(-3.2,4) B2(-2.4,4) B3(-1.6,4) B7(1.6,4) B8(2.4,4) B9(3.2,4) C1(-3.2,3.2) C2(-2.4,3.2) C3(-1.6,3.2) C7(1.6,3.2) C8(2.4,3.2) C9(3.2,3.2) D1(-3.2,2.4) D2(-2.4,2.4) D3(-1.6,2.4) D7(1.6,2.4) D8(2.4,2.4) D9(3.2,2.4) E1(-3.2,1.6) E2(-2.4,1.6) E3(-1.6,1.6) E7(1.6,1.6) E8(2.4,1.6) E9(3.2,1.6) F1(-3.2,0.8) F2(-2.4,0.8) F3(-1.6,0.8) F7(1.6,0.8) F8(2.4,0.8) F9(3.2,0.8) G1(-3.2,0) G2(-2.4,0) G3(-1.6,0) G7(1.6,0) G8(2.4,0) G9(3.2,0) H1(-3.2,-0.8) H2(-2.4,-0.8) H3(-1.6,-0.8) H7(1.6,-0.8) H8(2.4,-0.8) H9(3.2,-0.8) J1(-3.2,-1.6) J2(-2.4,-1.6) J3(-1.6,-1.6) J7(1.6,-1.6) J8(2.4,-1.6) J9(3.2,-1.6) K1(-3.2,-2.4) K2(-2.4,-2.4) K3(-1.6,-2.4) K7(1.6,-2.4) K8(2.4,-2.4) K9(3.2,-2.4) L1(-3.2,-3.2) L2(-2.4,-3.2) L3(-1.6,-3.2) L7(1.6,-3.2) L8(2.4,-3.2) L9(3.2,-3.2) M1(-3.2,-4) M2(-2.4,-4) M3(-1.6,-4) M7(1.6,-4) M8(2.4,-4) M9(3.2,-4) N1(-3.2,-4.8) N2(-2.4,-4.8) N3(-1.6,-4.8) N7(1.6,-4.8) N8(2.4,-4.8) N9(3.2,-4.8)
FUSE_397_410X110_SMD_2-9
  rect 3.302x4.369 smd: 1(-5.045,0) 2(5.045,0)
HDR_1X3_440054-3_S_T_6-4
  rect 1.499x1.499 hole 0.813: 1(0,0)
  round 1.499 hole 0.813: 2(-2,0) 3(-4,0)
HDR_1X6_22052061_R_T_6-3
  rect 1.702x1.702 hole 1.016: 1(0,0)
  round 1.702 hole 1.016: 2(-2.54,0) 3(-5.08,0) 4(-7.62,0) 5(-10.16,0) 6(-12.7,0)
HDR_1X7_22284070_S_T_8-4
  rect 1.702x1.702 hole 1.016: 1(0,0)
  round 1.702 hole 1.016: 2(-2.54,0) 3(-5.08,0) 4(-7.62,0) 5(-10.16,0) 6(-12.7,0) 7(-15.24,0)
HDR_2X1_100_S_T_10-8
  rect 1.702x1.702 hole 1.016: 1(0,0)
  round 1.702 hole 1.016: 2(-2.54,0)
HDR_2X3_TSW-103-07-D_S_T_8-4
  rect 1.702x1.702 hole 1.016: 1(0,0)
  round 1.702 hole 1.016: 2(0,2.54) 3(2.54,0) 4(2.54,2.54) 5(5.08,0) 6(5.08,2.54)
HDR_2X5_TFC-105-01-D-A_S_T_5-6
  round 1.295 hole 1.422 unplated: (-1.59,0.635) (6.67,0.635)
  oval 0.914x1.295 hole 0.61: 1(0,0) 2(0,1.27) 3(1.27,0) 4(1.27,1.27) 5(2.54,0) 6(2.54,1.27) 7(3.81,0) 8(3.81,1.27) 9(5.08,0) 10(5.08,1.27)
HDR_2X10_TSW_100_S_T
  rect 1.702x1.702 hole 1.016: 1(0,0)
  round 1.702 hole 1.016: 2(0,-2.54) 3(-2.54,0) 4(-2.54,-2.54) 5(-5.08,0) 6(-5.08,-2.54) 7(-7.62,0) 8(-7.62,-2.54) 9(-10.16,0) 10(-10.16,-2.54) 11(-12.7,0) 12(-12.7,-2.54) 13(-15.24,0) 14(-15.24,-2.54) 15(-17.78,0) 16(-17.78,-2.54) 17(-20.32,0) 18(-20.32,-2.54) 19(-22.86,0) 20(-22.86,-2.54)
HDR_3X1_100_S_T
  rect 1.803x1.803 hole 1.118: 1(0,0)
  round 1.803 hole 1.118: 2(-2.54,0) 3(-5.08,0)
HDR_5X1_100_S_T_8-4
  rect 1.702x1.702 hole 1.016: 1(0,0)
  round 1.702 hole 1.016: 2(-2.54,0) 3(-5.08,0) 4(-7.62,0) 5(-10.16,0)
HDR_5X1_100_S_T_11-2
  rect 1.702x1.702 hole 1.016: 1(0,0)
  round 1.702 hole 1.016: 2(-2.54,0) 3(-5.08,0) 4(-7.62,0) 5(-10.16,0)
HDR_6X1_100_S_T
  rect 1.88x1.88 hole 1.168: 1(0,0)
  round 1.88 hole 1.168: 2(-2.54,0) 3(-5.08,0) 4(-7.62,0) 5(-10.16,0) 6(-12.7,0)
IND4_ACM2012_90X50_SMD_1-3
  rect 0.762x0.406 smd: 1(-0.925,0.4) 2(-0.925,-0.4) 3(0.925,-0.4) 4(0.925,0.4)
IND_74439346068_260X270_SMD_6-1
  rect 1.448x5.512 smd: 1(-2,0) 2(2,0)
IND_ETQP4MKVK_350X330_SMD_4
  rect 2.413x5.334 smd: 1(-3.619,0) 2(3.619,0)
IND_ETQP5MYFM_310X290_SMD_5-4
  rect 3.607x3.607 smd: 1(-3.2,0) 2(3.2,0)
IND_IHLP2020AB_210X210_SMD_1-2
  rect 1.905x2.794 smd: 1(-2.425,0) 2(2.425,0)
IND_XEL4030_170X170_SMD_1-6
  rect 0.991x3.404 smd: 1(-1.185,0) 2(1.185,0)
IND_XFL4020_170X170_SMD_2-1
  rect 1.448x3.708 smd: 1(-1.225,0) 2(1.225,0)
LED3_SML-LX15IGC_120X120_SMD_1
  rect 1.499x1.499 smd: 1(-1.4,-0.95) 2(-1.4,0.95) 3(1.4,0)
LED_0402_0-3
  rect 0.61x0.508 smd: 1(0,-0.45) 2(0,0.45)
LED_0603_0-7
  rect 0.762x0.838 smd: 1(-0.7,0) 2(0.7,0)
LED_0603_0-8
  rect 1.016x1.067 smd: 1(-0.95,0) 2(0.95,0)
LED_0805
  rect 0.889x1.295 smd: 1(-0.8,0) 2(0.8,0)
LED_0805_0-7
  rect 0.914x1.397 smd: 1(-1,0) 2(1,0)
LQFP64_19-68_390X390_1-6
  rect 1.499x0.305 smd: 1(-5.7,3.75) 2(-5.7,3.25) 3(-5.7,2.75) 4(-5.7,2.25) 5(-5.7,1.75) 6(-5.7,1.25) 7(-5.7,0.75) 8(-5.7,0.25) 9(-5.7,-0.25) 10(-5.7,-0.75) 11(-5.7,-1.25) 12(-5.7,-1.75) 13(-5.7,-2.25) 14(-5.7,-2.75) 15(-5.7,-3.25) 16(-5.7,-3.75) 33(5.7,-3.75) 34(5.7,-3.25) 35(5.7,-2.75) 36(5.7,-2.25) 37(5.7,-1.75) 38(5.7,-1.25) 39(5.7,-0.75) 40(5.7,-0.25) 41(5.7,0.25) 42(5.7,0.75) 43(5.7,1.25) 44(5.7,1.75) 45(5.7,2.25) 46(5.7,2.75) 47(5.7,3.25) 48(5.7,3.75)
  rect 0.305x1.499 smd: 17(-3.75,-5.7) 18(-3.25,-5.7) 19(-2.75,-5.7) 20(-2.25,-5.7) 21(-1.75,-5.7) 22(-1.25,-5.7) 23(-0.75,-5.7) 24(-0.25,-5.7) 25(0.25,-5.7) 26(0.75,-5.7) 27(1.25,-5.7) 28(1.75,-5.7) 29(2.25,-5.7) 30(2.75,-5.7) 31(3.25,-5.7) 32(3.75,-5.7) 49(3.75,5.7) 50(3.25,5.7) 51(2.75,5.7) 52(2.25,5.7) 53(1.75,5.7) 54(1.25,5.7) 55(0.75,5.7) 56(0.25,5.7) 57(-0.25,5.7) 58(-0.75,5.7) 59(-1.25,5.7) 60(-1.75,5.7) 61(-2.25,5.7) 62(-2.75,5.7) 63(-3.25,5.7) 64(-3.75,5.7)
MSOP8_25-59_125X125_1-1
  rect 1.651x0.457 smd: 1(-2.3,0.975) 2(-2.3,0.325) 3(-2.3,-0.325) 4(-2.3,-0.975) 5(2.3,-0.975) 6(2.3,-0.325) 7(2.3,0.325) 8(2.3,0.975)
MSOP10_19-68_120X120
  rect 1.092x0.254 smd: 1(-2.15,1) 2(-2.15,0.5) 3(-2.15,0) 4(-2.15,-0.5) 5(-2.15,-1) 6(2.15,-1) 7(2.15,-0.5) 8(2.15,0) 9(2.15,0.5) 10(2.15,1)
MSOP10_19-68_120X120_1-1
  rect 1.448x0.305 smd: 1(-2.2,1) 2(-2.2,0.5) 3(-2.2,0) 4(-2.2,-0.5) 5(-2.2,-1) 6(2.2,-1) 7(2.2,-0.5) 8(2.2,0) 9(2.2,0.5) 10(2.2,1)
OSC4_KC2520B_100X80_SMD
  rect 1.041x0.94 smd: 1(-0.925,-0.725) 2(0.925,-0.725) 3(0.925,0.725) 4(-0.925,0.725)
QFN10_15-74_75X60
  rect 0.813x0.203 smd: 1(-0.7,0.2) 2(-0.7,-0.2) 6(0.7,-0.2) 7(0.7,0.2)
  rect 0.203x0.813 smd: 3(-0.4,-0.9) 4(0,-0.9) 5(0.4,-0.9) 8(0.4,0.9) 9(0,0.9) 10(-0.4,0.9)
QFN16_19-68_120X120_1
  rect 0.864x0.305 smd: 1(-1.5,0.75) 2(-1.5,0.25) 3(-1.5,-0.25) 4(-1.5,-0.75) 9(1.5,-0.75) 10(1.5,-0.25) 11(1.5,0.25) 12(1.5,0.75)
  rect 0.305x0.864 smd: 5(-0.75,-1.5) 6(-0.25,-1.5) 7(0.25,-1.5) 8(0.75,-1.5) 13(0.75,1.5) 14(0.25,1.5) 15(-0.25,1.5) 16(-0.75,1.5)
  rect 1.549x1.549 smd: 17(0,0)
QFN16_19-68_160X140
  rect 0.864x0.279 smd: 1(-1.975,-0.75) 8(1.975,-0.75) 9(1.975,0.75) 16(-1.975,0.75)
  rect 0.279x0.864 smd: 2(-1.25,-1.725) 3(-0.75,-1.725) 4(-0.25,-1.725) 5(0.25,-1.725) 6(0.75,-1.725) 7(1.25,-1.725) 10(1.25,1.725) 11(0.75,1.725) 12(0.25,1.725) 13(-0.25,1.725) 14(-0.75,1.725) 15(-1.25,1.725)
  rect 2.54x2.057 smd: 17(0,0)
QFN20_19-68_185X145_1
  rect 0.864x0.279 smd: 1(-2.225,-0.75) 10(2.225,-0.75) 11(2.225,0.75) 20(-2.225,0.75)
  rect 0.279x0.864 smd: 2(-1.75,-1.725) 3(-1.25,-1.725) 4(-0.75,-1.725) 5(-0.25,-1.725) 6(0.25,-1.725) 7(0.75,-1.725) 8(1.25,-1.725) 9(1.75,-1.725) 12(1.75,1.725) 13(1.25,1.725) 14(0.75,1.725) 15(0.25,1.725) 16(-0.25,1.725) 17(-0.75,1.725) 18(-1.25,1.725) 19(-1.75,1.725)
  rect 3.15x2.159 smd: 21(0,0)
QFN24_19-68_165X165
  rect 0.864x0.305 smd: 1(-1.975,1.25) 2(-1.975,0.75) 3(-1.975,0.25) 4(-1.975,-0.25) 5(-1.975,-0.75) 6(-1.975,-1.25) 13(1.975,-1.25) 14(1.975,-0.75) 15(1.975,-0.25) 16(1.975,0.25) 17(1.975,0.75) 18(1.975,1.25)
  rect 0.305x0.864 smd: 7(-1.25,-1.975) 8(-0.75,-1.975) 9(-0.25,-1.975) 10(0.25,-1.975) 11(0.75,-1.975) 12(1.25,-1.975) 19(1.25,1.975) 20(0.75,1.975) 21(0.25,1.975) 22(-0.25,1.975) 23(-0.75,1.975) 24(-1.25,1.975)
  rect 2.718x2.718 smd: 25(0,0)
QFN24_19-68_220X140_1
  rect 0.838x0.279 smd: 1(-2.725,-0.75) 12(2.725,-0.75) 13(2.725,0.75) 24(-2.725,0.75)
  rect 0.279x0.838 smd: 2(-2.25,-1.725) 3(-1.75,-1.725) 4(-1.25,-1.725) 5(-0.75,-1.725) 6(-0.25,-1.725) 7(0.25,-1.725) 8(0.75,-1.725) 9(1.25,-1.725) 10(1.75,-1.725) 11(2.25,-1.725) 14(2.25,1.725) 15(1.75,1.725) 16(1.25,1.725) 17(0.75,1.725) 18(0.25,1.725) 19(-0.25,1.725) 20(-0.75,1.725) 21(-1.25,1.725) 22(-1.75,1.725) 23(-2.25,1.725)
  custom 0.508x0.508 smd: 25(0,0)
QFN32_19-68_200X200
  rect 0.838x0.305 smd: 1(-2.5,1.75) 2(-2.5,1.25) 3(-2.5,0.75) 4(-2.5,0.25) 5(-2.5,-0.25) 6(-2.5,-0.75) 7(-2.5,-1.25) 8(-2.5,-1.75) 17(2.5,-1.75) 18(2.5,-1.25) 19(2.5,-0.75) 20(2.5,-0.25) 21(2.5,0.25) 22(2.5,0.75) 23(2.5,1.25) 24(2.5,1.75)
  rect 0.305x0.838 smd: 9(-1.75,-2.5) 10(-1.25,-2.5) 11(-0.75,-2.5) 12(-0.25,-2.5) 13(0.25,-2.5) 14(0.75,-2.5) 15(1.25,-2.5) 16(1.75,-2.5) 25(1.75,2.5) 26(1.25,2.5) 27(0.75,2.5) 28(0.25,2.5) 29(-0.25,2.5) 30(-0.75,2.5) 31(-1.25,2.5) 32(-1.75,2.5)
  rect 3.556x3.556 smd: 33(0,0)
QFN32_19-68_200X200_1
  rect 0.838x0.305 smd: 1(-2.5,1.75) 2(-2.5,1.25) 3(-2.5,0.75) 4(-2.5,0.25) 5(-2.5,-0.25) 6(-2.5,-0.75) 7(-2.5,-1.25) 8(-2.5,-1.75) 17(2.5,-1.75) 18(2.5,-1.25) 19(2.5,-0.75) 20(2.5,-0.25) 21(2.5,0.25) 22(2.5,0.75) 23(2.5,1.25) 24(2.5,1.75)
  rect 0.305x0.838 smd: 9(-1.75,-2.5) 10(-1.25,-2.5) 11(-0.75,-2.5) 12(-0.25,-2.5) 13(0.25,-2.5) 14(0.75,-2.5) 15(1.25,-2.5) 16(1.75,-2.5) 25(1.75,2.5) 26(1.25,2.5) 27(0.75,2.5) 28(0.25,2.5) 29(-0.25,2.5) 30(-0.75,2.5) 31(-1.25,2.5) 32(-1.75,2.5)
  rect 3.556x3.556 smd: 33(0,0)
QFN40_19-68_240X240_0-9
  rect 0.838x0.305 smd: 1(-3,2.25) 2(-3,1.75) 3(-3,1.25) 4(-3,0.75) 5(-3,0.25) 6(-3,-0.25) 7(-3,-0.75) 8(-3,-1.25) 9(-3,-1.75) 10(-3,-2.25) 21(3,-2.25) 22(3,-1.75) 23(3,-1.25) 24(3,-0.75) 25(3,-0.25) 26(3,0.25) 27(3,0.75) 28(3,1.25) 29(3,1.75) 30(3,2.25)
  rect 0.305x0.838 smd: 11(-2.25,-3) 12(-1.75,-3) 13(-1.25,-3) 14(-0.75,-3) 15(-0.25,-3) 16(0.25,-3) 17(0.75,-3) 18(1.25,-3) 19(1.75,-3) 20(2.25,-3) 31(2.25,3) 32(1.75,3) 33(1.25,3) 34(0.75,3) 35(0.25,3) 36(-0.25,3) 37(-0.75,3) 38(-1.25,3) 39(-1.75,3) 40(-2.25,3)
  rect 3.556x3.556 smd: 41(0,0)
QFN48_19-68_280X280_1
  rect 0.813x0.305 smd: 1(-3.5,2.75) 2(-3.5,2.25) 3(-3.5,1.75) 4(-3.5,1.25) 5(-3.5,0.75) 6(-3.5,0.25) 7(-3.5,-0.25) 8(-3.5,-0.75) 9(-3.5,-1.25) 10(-3.5,-1.75) 11(-3.5,-2.25) 12(-3.5,-2.75) 25(3.5,-2.75) 26(3.5,-2.25) 27(3.5,-1.75) 28(3.5,-1.25) 29(3.5,-0.75) 30(3.5,-0.25) 31(3.5,0.25) 32(3.5,0.75) 33(3.5,1.25) 34(3.5,1.75) 35(3.5,2.25) 36(3.5,2.75)
  rect 0.305x0.813 smd: 13(-2.75,-3.5) 14(-2.25,-3.5) 15(-1.75,-3.5) 16(-1.25,-3.5) 17(-0.75,-3.5) 18(-0.25,-3.5) 19(0.25,-3.5) 20(0.75,-3.5) 21(1.25,-3.5) 22(1.75,-3.5) 23(2.25,-3.5) 24(2.75,-3.5) 37(2.75,3.5) 38(2.25,3.5) 39(1.75,3.5) 40(1.25,3.5) 41(0.75,3.5) 42(0.25,3.5) 43(-0.25,3.5) 44(-0.75,3.5) 45(-1.25,3.5) 46(-1.75,3.5) 47(-2.25,3.5) 48(-2.75,3.5)
  rect 5.639x5.639 smd: 49(0,0)
RES0201
  rect 0.356x0.33 smd: 1(-0.28,0) 2(0.28,0)
RES0402
  rect 0.483x0.508 smd: 1(-0.42,0) 2(0.42,0)
RES0402_0-5
  rect 0.483x0.508 smd: 1(-0.42,0) 2(0.42,0)
RES0603
  rect 0.711x0.889 smd: 1(-0.7,0) 2(0.7,0)
RES0603_0-5
  rect 0.711x0.889 smd: 1(-0.7,0) 2(0.7,0)
RES0603_0-75
  rect 0.711x0.889 smd: 1(-0.7,0) 2(0.7,0)
RES0815_0-75
  rect 1.041x4.039 smd: 1(-0.95,0) 2(0.95,0)
RES1206
  rect 1.067x1.753 smd: 1(-1.45,0) 2(1.45,0)
RES1206-4TERM_0-75
  rect 1.753x1.092 smd: 1(-1.375,0.7) 2(-1.375,-0.7) 3(1.375,-0.7) 4(1.375,0.7)
RES2512-4TERM_0-75
  rect 3.302x1.397 smd: 1(-2.15,1.8) 2(-2.15,-1.8) 3(2.15,-1.8) 4(2.15,1.8)
RESA_0402-8
  rect 0.406x0.635 smd: 1(-1.813,-0.75) 8(1.813,-0.75) 9(1.813,0.75) 16(-1.813,0.75)
  rect 0.279x0.635 smd: 2(-1.25,-0.75) 3(-0.75,-0.75) 4(-0.25,-0.75) 5(0.25,-0.75) 6(0.75,-0.75) 7(1.25,-0.75) 10(1.25,0.75) 11(0.75,0.75) 12(0.25,0.75) 13(-0.25,0.75) 14(-0.75,0.75) 15(-1.25,0.75)
RESA_EXB28V_0402-4_0-5
  rect 0.533x0.508 smd: 1(-0.887,-0.45) 4(0.887,-0.45) 5(0.887,0.45) 8(-0.887,0.45)
  rect 0.254x0.508 smd: 2(-0.25,-0.45) 3(0.25,-0.45) 6(0.25,0.45) 7(-0.25,0.45)
RESA_EXBN8V_0402-4_0-6
  rect 0.61x0.381 smd: 1(-0.544,0.807) 4(-0.544,-0.807) 5(0.544,-0.807) 8(0.544,0.807)
  rect 0.61x0.254 smd: 2(-0.544,0.25) 3(-0.544,-0.25) 6(0.544,-0.25) 7(0.544,0.25)
SC70-5
  rect 0.762x0.406 smd: 1(-1,0.65) 2(-1,0) 3(-1,-0.65) 4(1,-0.65) 5(1,0.65)
SC70-5_1-1
  rect 0.762x0.406 smd: 1(-1,0.65) 2(-1,0) 3(-1,-0.65) 4(1,-0.65) 5(1,0.65)
SC70-6
  rect 0.762x0.406 smd: 1(-1,0.65) 2(-1,0) 3(-1,-0.65) 4(1,-0.65) 5(1,0) 6(1,0.65)
SOIC8_1-8
  rect 1.346x0.559 smd: 1(-2.6,1.905) 2(-2.6,0.635) 3(-2.6,-0.635) 4(-2.6,-1.905) 5(2.6,-1.905) 6(2.6,-0.635) 7(2.6,0.635) 8(2.6,1.905)
SOIC16_1-8
  rect 1.549x0.61 smd: 1(-2.7,4.445) 2(-2.7,3.175) 3(-2.7,1.905) 4(-2.7,0.635) 5(-2.7,-0.635) 6(-2.7,-1.905) 7(-2.7,-3.175) 8(-2.7,-4.445) 9(2.7,-4.445) 10(2.7,-3.175) 11(2.7,-1.905) 12(2.7,-0.635) 13(2.7,0.635) 14(2.7,1.905) 15(2.7,3.175) 16(2.7,4.445)
SON6_19-68_40X60_0-6
  rect 0.762x0.254 smd: 1(-0.5,0.5) 2(-0.5,0) 3(-0.5,-0.5) 4(0.5,-0.5) 5(0.5,0) 6(0.5,0.5)
SON6_19-68_40X60_PB_0-6
  rect 0.356x0.305 smd: 1(-0.3,0.5) 2(-0.3,0) 3(-0.3,-0.5) 4(0.3,-0.5) 5(0.3,0) 6(0.3,0.5)
SON6_19-68_60X45
  rect 0.305x0.508 smd: 1(-0.5,-0.385) 2(0,-0.385) 3(0.5,-0.385) 4(0.5,0.385) 5(0,0.385) 6(-0.5,0.385)
SON6_25-59_85X85
  rect 0.508x0.356 smd: 1(-1,0.65) 2(-1,0) 3(-1,-0.65) 4(1,-0.65) 5(1,0) 6(1,0.65)
  rect 1.092x1.702 smd: 7(0,0)
SON6_25-59_85X85_0-8
  rect 0.508x0.356 smd: 1(-1,0.65) 2(-1,0) 3(-1,-0.65) 4(1,-0.65) 5(1,0) 6(1,0.65)
  rect 1.092x1.702 smd: 7(0,0)
SON8_25-59_130X130_1
  rect 0.94x0.356 smd: 1(-1.55,0.975) 2(-1.55,0.325) 3(-1.55,-0.325) 4(-1.55,-0.975) 5(1.55,-0.975) 6(1.55,-0.325) 7(1.55,0.325) 8(1.55,0.975)
  rect 1.753x2.515 smd: 9(0,0)
SON10_19-68_125X125_1
  rect 0.838x0.279 smd: 1(-1.475,1) 2(-1.475,0.5) 3(-1.475,0) 4(-1.475,-0.5) 5(-1.475,-1) 6(1.475,-1) 7(1.475,-0.5) 8(1.475,0) 9(1.475,0.5) 10(1.475,1)
  custom 0.412x0.412 smd: 11(0,0)
SOT23-5
  rect 0.889x0.559 smd: 1(-1.2,0.95) 2(-1.2,0) 3(-1.2,-0.95) 4(1.2,-0.95) 5(1.2,0.95)
SOT23-5_1-5
  rect 0.889x0.559 smd: 1(-1.2,0.95) 2(-1.2,0) 3(-1.2,-0.95) 4(1.2,-0.95) 5(1.2,0.95)
SOT23-6_1-1
  rect 1.092x0.61 smd: 1(-1.35,0.95) 2(-1.35,0) 3(-1.35,-0.95) 4(1.35,-0.95) 5(1.35,0) 6(1.35,0.95)
SOT23-6_1-5
  rect 0.889x0.559 smd: 1(-1.2,0.95) 2(-1.2,0) 3(-1.2,-0.95) 4(1.2,-0.95) 5(1.2,0) 6(1.2,0.95)
SOT23-123
  rect 0.838x0.61 smd: 1(-1.05,0.95) 2(-1.05,-0.95) 3(1.05,0)
SOT23-123_1-2
  rect 0.838x0.61 smd: 1(-1.05,0.95) 2(-1.05,-0.95) 3(1.05,0)
SW2_50X200_160X210_SMD
  rect 0.762x1.6 smd: 1(-0.635,-2.54) 2(0.635,-2.54) 3(0.635,2.54) 4(-0.635,2.54)
SW3_ATE1F-6M3_370X710_TH_5-6
  rect 1.702x1.702 hole 1.016: 1(0,0)
  round 1.702 hole 1.016: 2(-2.54,0) 3(-5.08,0) SH1(-5.08,-7.62) SH2(0,-7.62)
SW4_SKHMQLE010_240X260_SMD_3-1
  rect 1.6x1.321 smd: 1(-4.2,2.25) 2(4.2,2.25) 3(-4.2,-2.25) 4(4.2,-2.25) 5(4.2,0)
SW10_50_550X230_SMD
  rect 0.762x1.27 smd: 1(-5.715,-3.81) 2(-4.445,-3.81) 3(-3.175,-3.81) 4(-1.905,-3.81) 5(-0.635,-3.81) 6(0.635,-3.81) 7(1.905,-3.81) 8(3.175,-3.81) 9(4.445,-3.81) 10(5.715,-3.81) 11(5.715,3.81) 12(4.445,3.81) 13(3.175,3.81) 14(1.905,3.81) 15(0.635,3.81) 16(-0.635,3.81) 17(-1.905,3.81) 18(-3.175,3.81) 19(-4.445,3.81) 20(-5.715,3.81)
TO_SOT23-123
  rect 0.838x0.61 smd: 1(-1.05,0.95) 2(-1.05,-0.95) 3(1.05,0)
TP40_SMD
  round 1.016 smd: 1(0,0)
TP_40X65
  round 1.651 hole 1.016: 1(0,0)
TP_CIR67D40_TH_4-6
  round 1.702 hole 1.016: 1(0,0)
TPBGA24_39-37_240X320_1-2
  round 0.356 smd: A2(-1,2) A3(0,2) A4(1,2) A5(2,2) B1(-2,1) B2(-1,1) B3(0,1) B4(1,1) B5(2,1) C1(-2,0) C2(-1,0) C3(0,0) C4(1,0) C5(2,0) D1(-2,-1) D2(-1,-1) D3(0,-1) D4(1,-1) D5(2,-1) E1(-2,-2) E2(-1,-2) E3(0,-2) E4(1,-2) E5(2,-2)
TQFP128_15-74_550X550_1-2
  rect 1.499x0.203 smd: 1(-7.7,6.2) 2(-7.7,5.8) 3(-7.7,5.4) 4(-7.7,5) 5(-7.7,4.6) 6(-7.7,4.2) 7(-7.7,3.8) 8(-7.7,3.4) 9(-7.7,3) 10(-7.7,2.6) 11(-7.7,2.2) 12(-7.7,1.8) 13(-7.7,1.4) 14(-7.7,1) 15(-7.7,0.6) 16(-7.7,0.2) 17(-7.7,-0.2) 18(-7.7,-0.6) 19(-7.7,-1) 20(-7.7,-1.4) 21(-7.7,-1.8) 22(-7.7,-2.2) 23(-7.7,-2.6) 24(-7.7,-3) 25(-7.7,-3.4) 26(-7.7,-3.8) 27(-7.7,-4.2) 28(-7.7,-4.6) 29(-7.7,-5) 30(-7.7,-5.4) 31(-7.7,-5.8) 32(-7.7,-6.2) 65(7.7,-6.2) 66(7.7,-5.8) 67(7.7,-5.4) 68(7.7,-5) 69(7.7,-4.6) 70(7.7,-4.2) 71(7.7,-3.8) 72(7.7,-3.4) 73(7.7,-3) 74(7.7,-2.6) 75(7.7,-2.2) 76(7.7,-1.8) 77(7.7,-1.4) 78(7.7,-1) 79(7.7,-0.6) 80(7.7,-0.2) 81(7.7,0.2) 82(7.7,0.6) 83(7.7,1) 84(7.7,1.4) 85(7.7,1.8) 86(7.7,2.2) 87(7.7,2.6) 88(7.7,3) 89(7.7,3.4) 90(7.7,3.8) 91(7.7,4.2) 92(7.7,4.6) 93(7.7,5) 94(7.7,5.4) 95(7.7,5.8) 96(7.7,6.2)
  rect 0.203x1.499 smd: 33(-6.2,-7.7) 34(-5.8,-7.7) 35(-5.4,-7.7) 36(-5,-7.7) 37(-4.6,-7.7) 38(-4.2,-7.7) 39(-3.8,-7.7) 40(-3.4,-7.7) 41(-3,-7.7) 42(-2.6,-7.7) 43(-2.2,-7.7) 44(-1.8,-7.7) 45(-1.4,-7.7) 46(-1,-7.7) 47(-0.6,-7.7) 48(-0.2,-7.7) 49(0.2,-7.7) 50(0.6,-7.7) 51(1,-7.7) 52(1.4,-7.7) 53(1.8,-7.7) 54(2.2,-7.7) 55(2.6,-7.7) 56(3,-7.7) 57(3.4,-7.7) 58(3.8,-7.7) 59(4.2,-7.7) 60(4.6,-7.7) 61(5,-7.7) 62(5.4,-7.7) 63(5.8,-7.7) 64(6.2,-7.7) 97(6.2,7.7) 98(5.8,7.7) 99(5.4,7.7) 100(5,7.7) 101(4.6,7.7) 102(4.2,7.7) 103(3.8,7.7) 104(3.4,7.7) 105(3,7.7) 106(2.6,7.7) 107(2.2,7.7) 108(1.8,7.7) 109(1.4,7.7) 110(1,7.7) 111(0.6,7.7) 112(0.2,7.7) 113(-0.2,7.7) 114(-0.6,7.7) 115(-1,7.7) 116(-1.4,7.7) 117(-1.8,7.7) 118(-2.2,7.7) 119(-2.6,7.7) 120(-3,7.7) 121(-3.4,7.7) 122(-3.8,7.7) 123(-4.2,7.7) 124(-4.6,7.7) 125(-5,7.7) 126(-5.4,7.7) 127(-5.8,7.7) 128(-6.2,7.7)
TSSOP8_25-59_125X180_1-2
  rect 1.499x0.457 smd: 1(-2.9,0.975) 2(-2.9,0.325) 3(-2.9,-0.325) 4(-2.9,-0.975) 5(2.9,-0.975) 6(2.9,-0.325) 7(2.9,0.325) 8(2.9,0.975)
TSSOP16_25-59_205X180
  rect 1.6x0.356 smd: 1(-2.8,2.275) 2(-2.8,1.625) 3(-2.8,0.975) 4(-2.8,0.325) 5(-2.8,-0.325) 6(-2.8,-0.975) 7(-2.8,-1.625) 8(-2.8,-2.275) 9(2.8,-2.275) 10(2.8,-1.625) 11(2.8,-0.975) 12(2.8,-0.325) 13(2.8,0.325) 14(2.8,0.975) 15(2.8,1.625) 16(2.8,2.275)
TSSOP16_25-59_205X180_1-2
  rect 1.6x0.356 smd: 1(-2.8,2.275) 2(-2.8,1.625) 3(-2.8,0.975) 4(-2.8,0.325) 5(-2.8,-0.325) 6(-2.8,-0.975) 7(-2.8,-1.625) 8(-2.8,-2.275) 9(2.8,-2.275) 10(2.8,-1.625) 11(2.8,-0.975) 12(2.8,-0.325) 13(2.8,0.325) 14(2.8,0.975) 15(2.8,1.625) 16(2.8,2.275)
unnamed
  round 2.616 hole 2.743 unplated: (0,0)
unnamed#3
  round 1.6 hole 1.727 unplated: (-12.862,12.862) (-12.862,-12.862) (12.862,12.862) (12.862,-12.862)
  round 0.737 hole 0.864 unplated: (-12.862,-7.782) (12.862,10.322)
UQFN10_19-68_80X60_0-6
  rect 0.584x0.305 smd: 1(-0.635,0.75) 4(-0.635,-0.75) 6(0.635,-0.75) 9(0.635,0.75)
  rect 0.584x0.254 smd: 2(-0.637,0.25) 3(-0.637,-0.25) 7(0.637,-0.25) 8(0.637,0.25)
  rect 0.305x0.635 smd: 5(0,-0.86) 10(0,0.86)
UQFN16_15-74_105X75_0-6
  rect 0.203x0.762 smd: 1(-0.6,-0.725)
  rect 0.203x0.66 smd: 2(-0.2,-0.775) 3(0.2,-0.775) 4(0.6,-0.775) 9(0.6,0.775) 10(0.2,0.775) 11(-0.2,0.775) 12(-0.6,0.775)
  rect 0.635x0.203 smd: 5(1.188,-0.6) 8(1.188,0.6) 13(-1.188,0.6) 15(-1.188,-0.2) 16(-1.188,-0.6)
  rect 0.66x0.203 smd: 6(1.175,-0.2) 7(1.175,0.2) 14(-1.175,0.2)
VFBGA153_19-68_460X520_1-2
  round 0.203 smd: A1(-3.25,3.25) A2(-2.75,3.25) A3(-2.25,3.25) A4(-1.75,3.25) A5(-1.25,3.25) A6(-0.75,3.25) A7(-0.25,3.25) A8(0.25,3.25) B7(-0.25,2.75) C1(-3.25,2.25) D1(-3.25,1.75) N1(-3.25,-2.75) P1(-3.25,-3.25)
  round 0.254 smd: A9(0.75,3.25) A10(1.25,3.25) A11(1.75,3.25) A12(2.25,3.25) A13(2.75,3.25) A14(3.25,3.25) B1(-3.25,2.75) B2(-2.75,2.75) B3(-2.25,2.75) B4(-1.75,2.75) B5(-1.25,2.75) B6(-0.75,2.75) B8(0.25,2.75) B9(0.75,2.75) B10(1.25,2.75) B11(1.75,2.75) B12(2.25,2.75) B13(2.75,2.75) B14(3.25,2.75) C2(-2.75,2.25) C3(-2.25,2.25) C4(-1.75,2.25) C5(-1.25,2.25) C6(-0.75,2.25) C7(-0.25,2.25) C8(0.25,2.25) C9(0.75,2.25) C10(1.25,2.25) C11(1.75,2.25) C12(2.25,2.25) C13(2.75,2.25) C14(3.25,2.25) D2(-2.75,1.75) D3(-2.25,1.75) D4(-1.75,1.75) D12(2.25,1.75) D13(2.75,1.75) D14(3.25,1.75) E1(-3.25,1.25) E2(-2.75,1.25) E3(-2.25,1.25) E5(-1.25,1.25) E6(-0.75,1.25) E7(-0.25,1.25) E8(0.25,1.25) E9(0.75,1.25) E10(1.25,1.25) E12(2.25,1.25) E13(2.75,1.25) E14(3.25,1.25) F1(-3.25,0.75) F2(-2.75,0.75) F3(-2.25,0.75) F5(-1.25,0.75) F10(1.25,0.75) F12(2.25,0.75) F13(2.75,0.75) F14(3.25,0.75) G1(-3.25,0.25) G2(-2.75,0.25) G3(-2.25,0.25) G5(-1.25,0.25) G10(1.25,0.25) G12(2.25,0.25) G13(2.75,0.25) G14(3.25,0.25) H1(-3.25,-0.25) H2(-2.75,-0.25) H3(-2.25,-0.25) H5(-1.25,-0.25) H10(1.25,-0.25) H12(2.25,-0.25) H13(2.75,-0.25) H14(3.25,-0.25) J1(-3.25,-0.75) J2(-2.75,-0.75) J3(-2.25,-0.75) J5(-1.25,-0.75) J10(1.25,-0.75) J12(2.25,-0.75) J13(2.75,-0.75) J14(3.25,-0.75) K1(-3.25,-1.25) K2(-2.75,-1.25) K3(-2.25,-1.25) K5(-1.25,-1.25) K6(-0.75,-1.25) K7(-0.25,-1.25) K8(0.25,-1.25) K9(0.75,-1.25) K10(1.25,-1.25) K12(2.25,-1.25) K13(2.75,-1.25) K14(3.25,-1.25) L1(-3.25,-1.75) L2(-2.75,-1.75) L3(-2.25,-1.75) L12(2.25,-1.75) L13(2.75,-1.75) L14(3.25,-1.75) M1(-3.25,-2.25) M2(-2.75,-2.25) M3(-2.25,-2.25) M4(-1.75,-2.25) M5(-1.25,-2.25) M6(-0.75,-2.25) M7(-0.25,-2.25) M8(0.25,-2.25) M9(0.75,-2.25) M10(1.25,-2.25) M11(1.75,-2.25) M12(2.25,-2.25) M13(2.75,-2.25) M14(3.25,-2.25) N2(-2.75,-2.75) N3(-2.25,-2.75) N4(-1.75,-2.75) N5(-1.25,-2.75) N6(-0.75,-2.75) N7(-0.25,-2.75) N8(0.25,-2.75) N9(0.75,-2.75) N10(1.25,-2.75) N11(1.75,-2.75) N12(2.25,-2.75) N13(2.75,-2.75) N14(3.25,-2.75) P2(-2.75,-3.25) P3(-2.25,-3.25) P4(-1.75,-3.25) P5(-1.25,-3.25) P6(-0.75,-3.25) P7(-0.25,-3.25) P8(0.25,-3.25) P9(0.75,-3.25) P10(1.25,-3.25) P11(1.75,-3.25) P12(2.25,-3.25) P13(2.75,-3.25) P14(3.25,-3.25)
VQFNHR11_TPS62097_80X80_1
  rect 1.143x0.305 smd: 1(-0.675,0.225) 7(0.675,0.225)
  rect 2.489x0.305 smd: 2(0,-0.225)
  rect 0.254x0.584 smd: 3(-0.75,-0.912) 4(-0.25,-0.912) 5(0.25,-0.912) 6(0.75,-0.912) 8(0.75,0.912) 9(0.25,0.912) 10(-0.25,0.912) 11(-0.75,0.912)
VQFNHR16_TPS62480_100X120_1
  rect 1.397x0.356 smd: 1(-0.8,0.525) 2(-0.8,0) 3(-0.8,-0.525) 9(0.8,-0.525) 10(0.8,0) 11(0.8,0.525)
  rect 0.254x0.61 smd: 4(-1,-1.4) 5(-0.5,-1.4) 6(0,-1.4) 7(0.5,-1.4) 8(1,-1.4) 12(1,1.4) 13(0.5,1.4) 14(0,1.4) 15(-0.5,1.4) 16(-1,1.4)
VSONHR7_TPS62085_80X80_1
  rect 0.61x0.254 smd: 1(-0.9,0.75) 2(-0.9,0.25) 3(-0.9,-0.25) 4(-0.9,-0.75)
  rect 1.651x0.457 smd: 5(0.45,-0.6) 6(0.45,0) 7(0.45,0.6)
VSONP8_CSD18543Q_120X130_0-9
  rect 0.711x0.406 smd: 1(-1.55,0.975) 2(-1.55,0.325) 3(-1.55,-0.325) 4(-1.55,-0.975)
  rect 2.515x2.54 smd: 5(0.645,0)
VSSOP8_19-68_85X95_0-9
  rect 0.838x0.305 smd: 1(-1.55,0.75) 2(-1.55,0.25) 3(-1.55,-0.25) 4(-1.55,-0.75) 5(1.55,-0.75) 6(1.55,-0.25) 7(1.55,0.25) 8(1.55,0.75)
X2SON4_TLV71318P_40X40_0-4
  custom 0.077x0.077 smd: 1(-0.43,0.325) 2(-0.43,-0.325) 3(0.43,-0.325) 4(0.43,0.325)
  rect 0.584x0.584 smd rot 45: 5(0,0)
X2SON8_15-74_70X50
  rect 0.838x0.203 smd: 1(-0.55,0.6) 2(-0.55,0.2) 3(-0.55,-0.2) 4(-0.55,-0.6) 5(0.55,-0.6) 6(0.55,-0.2) 7(0.55,0.2) 8(0.55,0.6)
